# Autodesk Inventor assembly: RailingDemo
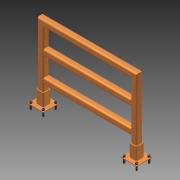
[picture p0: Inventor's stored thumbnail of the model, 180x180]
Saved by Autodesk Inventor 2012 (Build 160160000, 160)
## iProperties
Created: 2009-02
Part Number: RailingDemo
Document SubType Name: Assembly
Designer: Dave Reaume
Mass: 10373 g
Surface Area: 10870.3 cm^2
Volume: 3699.08 cm^3
Density: 2.80422 g/cm^3
Description: Railing Demonstration iLogic
RuleStatus: InUse
Author: reaumed
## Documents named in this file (6)
- C:\CMU\Datasets\Session 5\iLogic\Railing iLogic Sample Basic.iam
- C:\CMU\Datasets\Session 5\iLogic\Parts\TopRail.ipt
- C:\CMU\Datasets\Session 5\iLogic\Parts\Side Rail.ipt
- C:\CMU\Datasets\Session 5\iLogic\Parts\MiddleRail.ipt
- C:\CMU\Datasets\Session 5\iLogic\Parts\BottomPlate.ipt
- C:\CMU\Datasets\Session 5\iLogic\Sub Assemblies\BaseMount.iam
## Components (8 placed, 8 different names)
1. TopRail_1 — Mate:1, Mate:2, Flush:1, BottomPlateLoc, MiddleRailLoc
2. BottomPlate_1 — Mate:6, Mate:7, BottomPlateLoc
3. Side Rail_1 — Mate:1, Mate:2, Flush:1, Mate:6, Flush:5, Mate:9
4. Side Rail_2
5. BaseMount_1 [sub-assembly] — Mate:8, Flush:5, Mate:9
6. BaseMount_2 [sub-assembly]
7. MiddleRail_1 — Mate:4, Mate:5, MiddleRailLoc
8. MiddleRail:2
## Component patterns: Side Rail Pattern (2 elements), BaseMount Pattern (2 elements), MiddleRail Pattern (2 elements)
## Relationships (12: Mate 8, Flush 4)
- Mate:1: TopRail_1 ↔ Side Rail_1
- Mate:2: TopRail_1 ↔ Side Rail_1
- Flush:1: TopRail_1 ↔ Side Rail_1
- Mate:4: MiddleRail_1
- Mate:5: MiddleRail_1
- Mate:6: BottomPlate_1 ↔ Side Rail_1
- Mate:7: BottomPlate_1
- BottomPlateLoc [Flush]: TopRail_1 ↔ BottomPlate_1
- MiddleRailLoc [Flush]: TopRail_1 ↔ MiddleRail_1
- Mate:8: BaseMount_1
- Flush:5: Side Rail_1 ↔ BaseMount_1
- Mate:9: Side Rail_1 ↔ BaseMount_1
## Named parameters: BottomPlateLoc = 330.2 mm, MiddleRailLoc = 203.2 mm, MiddleRailSpacing = 203.2 mm
